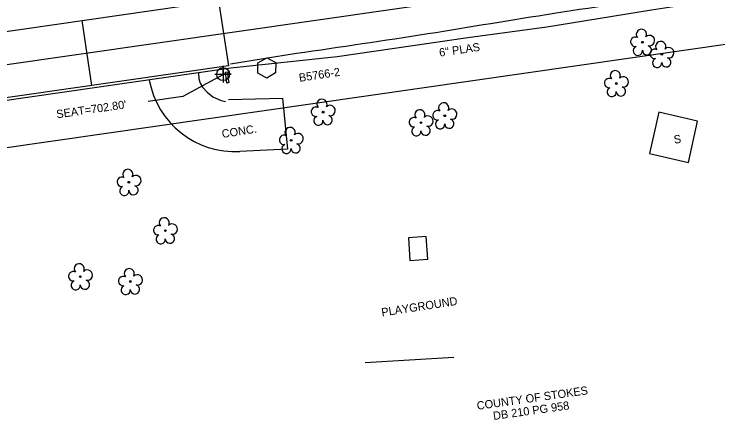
# Model space of a CAD drawing. Extents: x 1645945 to 2447332, y 713118 to 970361.
# Drawn here: x 1646888.7 to 1647146.3, y 969388.4 to 969536.8 of the extents above; entities that cross this region are included whole.
import ezdxf

# ---------------------------------------------------------------- set-up
doc = ezdxf.new("R2010")
doc.units = 0
for name, color, linetype in [('CTL Primary Horizontal and Vertical CELL', 7, 'Continuous'), ('CTL Primary Horizontal and Vertical Text', 7, 'Continuous'), ('Exist Building', 7, 'Continuous'), ('Exist Horizontal Alignment', 7, 'Continuous'), ('Exist Other Culture Area Outline', 7, 'Continuous'), ('Exist Other Culture Area Outline Text', 7, 'Continuous'), ('Exist Property Deed Book Text', 7, 'Continuous'), ('Exist Property Owner Text', 7, 'Continuous'), ('Exist Right of Way Line', 7, 'Continuous'), ('Exist Roads EOP', 7, 'Continuous'), ('Exist Structure Major Bridge Seam', 7, 'Continuous'), ('Exist Structure Major Bridge Seat Cogo Point CELL', 7, 'Continuous'), ('Exist Structure Major Bridge Seat Leader', 7, 'Continuous'), ('Exist Structure Major Bridge Seat Top Elevation', 7, 'Continuous'), ('Exist Structure Major Bridge WW', 7, 'Continuous'), ('Exist Structure Major Deck Tunnel Box Culvert', 7, 'Continuous'), ('Exist Utilities Sanitary Sewer Forced Main SUE LOS B', 7, 'Continuous'), ('Exist Utilities Sanitary Sewer Forced Main SUE LOS B Text', 7, 'Continuous'), ('Exist Utilities Sanitary Sewer Forced Main SUE LOS C', 7, 'Continuous'), ('Exist Vegetation Tree CELL', 7, 'Continuous')]:
    doc.layers.add(name, color=color, linetype=linetype)

msp = doc.modelspace()

# ---------------------------------------------------------------- linework, layer by layer
at = {"layer": 'CTL Primary Horizontal and Vertical CELL'}
msp.add_line((1646981.23, 969517.14), (1646981.23, 969517.14), dxfattribs=at)
msp.add_lwpolyline([(1646978, 969519.01), (1646981.25, 969520.82), (1646984.5, 969519.03), (1646984.45, 969515.31), (1646981.2, 969513.42), (1646978, 969515.23)], close=True, dxfattribs=at)
at = {"layer": 'Exist Building'}
msp.add_lwpolyline([(1647124.68, 969500.9), (1647121.22, 969485.85), (1647135.61, 969482.53), (1647138.83, 969497.65)], close=True, dxfattribs=at)
at = {"layer": 'Exist Horizontal Alignment'}
msp.add_line((1646298.92, 969433.93), (1647141.43, 969555.05), dxfattribs=at)
at = {"layer": 'Exist Other Culture Area Outline'}
msp.add_line((1647017.24, 969409.4), (1647049.61, 969411.4), dxfattribs=at)
for points in [[(1646956.19, 969515.23), (1646956.39, 969513.13), (1646956.89, 969511.58), (1646957.71, 969510.07), (1646959.36, 969508.27), (1646961.44, 969506.6), (1646964.56, 969505.2), (1646966.05, 969504.79)], [(1646967.24, 969505.55), (1646986.92, 969506.01), (1646988.76, 969487.37), (1646971.39, 969486.58)]]:
    msp.add_lwpolyline(points, dxfattribs=at)
msp.add_lwpolyline([(1647033.62, 969446.69), (1647040.13, 969447.17), (1647039.54, 969455.54), (1647033.02, 969455.06)], close=True, dxfattribs=at)
msp.add_arc((1646969.57, 969518.46), 31.93, 190.4277, 273.2578, dxfattribs=at)
at = {"layer": 'Exist Right of Way Line'}
msp.add_line((1646441.61, 969424.14), (1647154.4, 969526.61), dxfattribs=at)
at = {"layer": 'Exist Roads EOP'}
msp.add_line((1646992.05, 969522.32), (1646967.96, 969518.43), dxfattribs=at)
msp.add_spline([(1647731.3, 969935.45), (1647707.71, 969895.07), (1647684.27, 969857.13), (1647654.38, 969814.5), (1647624.46, 969779.25), (1647589.97, 969744.66), (1647553.5, 969714.01), (1647512.43, 969684.95), (1647469.3, 969658.19), (1647421.26, 969632.07), (1647375.68, 969609.9), (1647329.15, 969590.49), (1647286.02, 969576.26), (1647230.19, 969561.18), (1647183.04, 969552.75), (1647135.89, 969544.58), (1647086.4, 969536.99), (1647040.14, 969529.53), (1646992.05, 969522.32)], degree=3, dxfattribs=at)
at = {"layer": 'Exist Structure Major Bridge Seam'}
msp.add_line((1646913.54, 969534.4), (1646917.09, 969510.7), dxfattribs=at)
at = {"layer": 'Exist Structure Major Bridge Seat Cogo Point CELL'}
msp.add_lwpolyline([(1646962.24, 969514.82), (1646968.24, 969514.82), (1646965.24, 969514.82), (1646965.24, 969517.82), (1646965.24, 969511.82)], dxfattribs=at)
msp.add_circle((1646965.24, 969514.82), 2.34, dxfattribs=at)
at = {"layer": 'Exist Structure Major Bridge Seat Leader'}
msp.add_lwpolyline([(1646965.12, 969514.64), (1646950.54, 969506.66), (1646937.85, 969504.84)], dxfattribs=at)
at = {"layer": 'Exist Structure Major Bridge WW'}
msp.add_lwpolyline([(1646966.11, 969515.53), (1646966.98, 969515.63), (1646967.01, 969513.65), (1646967.38, 969511.73), (1646966.56, 969511.58), (1646966.32, 969513.6), (1646966.11, 969515.53)], dxfattribs=at)
at = {"layer": 'Exist Structure Major Deck Tunnel Box Culvert'}
msp.add_lwpolyline([(1646967.24, 969517.89), (1646619.97, 969468.05), (1646615.96, 969491.55), (1646963.57, 969541.6), (1646967.24, 969517.89)], dxfattribs=at)
at = {"layer": 'Exist Utilities Sanitary Sewer Forced Main SUE LOS B'}
msp.add_lwpolyline([(1646968.01, 969517.18), (1647007.02, 969521.34), (1647054.78, 969528.26), (1647083.72, 969532.15), (1647121.99, 969538.31), (1647141.01, 969541.29), (1647166.59, 969544.9), (1647192.95, 969550.61), (1647220.41, 969556.52), (1647247.21, 969563.1), (1647258.95, 969564.71), (1647268.16, 969566.61), (1647282, 969570.9)], dxfattribs=at)
at = {"layer": 'Exist Utilities Sanitary Sewer Forced Main SUE LOS C'}
msp.add_line((1646620.32, 969466.68), (1646968.01, 969517.18), dxfattribs=at)
at = {"layer": 'Exist Vegetation Tree CELL'}
for p, q in [((1647118.7, 969526.49), (1647118.7, 969526.49)), ((1647125.78, 969522.07), (1647125.78, 969522.07)), ((1647109.13, 969511.42), (1647109.13, 969511.42)), ((1647001.81, 969500.95), (1647001.81, 969500.95)), ((1647046.35, 969499.63), (1647046.35, 969499.63)), ((1647037.66, 969497.1), (1647037.66, 969497.1)), ((1646990.13, 969490.65), (1646990.13, 969490.65)), ((1646930.77, 969475.31), (1646930.77, 969475.31)), ((1646944.09, 969457.62), (1646944.09, 969457.62)), ((1646912.99, 969440.8), (1646912.99, 969440.8)), ((1646931.28, 969439.04), (1646931.28, 969439.04))]:
    msp.add_line(p, q, dxfattribs=at)
for centre in [(1647118.7, 969526.49), (1647125.78, 969522.07), (1647109.13, 969511.42), (1647001.81, 969500.95), (1647046.35, 969499.63), (1647037.66, 969497.1), (1646990.13, 969490.65), (1646930.77, 969475.31), (1646944.09, 969457.62), (1646912.99, 969440.8), (1646931.28, 969439.04)]:
    msp.add_circle(centre, 0.326, dxfattribs=at)
for centre, radius, start, end in [((1647118.31, 969529.37), 1.86, 330.1651, 219.7134), ((1647116.09, 969526.65), 1.73, 62.6636, 279.3457), ((1647121.25, 969527.08), 1.9, 257.1011, 134.1999), ((1647125.39, 969524.94), 1.86, 330.1651, 219.7134), ((1647117, 969523.37), 1.69, 111.5671, 6.231), ((1647120.37, 969523.59), 1.7, 181.2822, 74.56), ((1647123.17, 969522.22), 1.73, 62.6636, 279.3457), ((1647128.33, 969522.66), 1.9, 257.1011, 134.1999), ((1647127.45, 969519.17), 1.7, 181.2822, 74.56), ((1647124.08, 969518.95), 1.69, 111.5671, 6.231), ((1647108.75, 969514.29), 1.86, 330.1651, 219.7134), ((1647106.53, 969511.57), 1.73, 62.6636, 279.3457), ((1647111.68, 969512), 1.9, 257.1011, 134.1999), ((1647107.43, 969508.3), 1.69, 111.5671, 6.231), ((1647110.81, 969508.52), 1.7, 181.2822, 74.56), ((1647001.42, 969503.83), 1.86, 330.1651, 219.7134), ((1646999.2, 969501.11), 1.73, 62.6636, 279.3457), ((1647004.36, 969501.54), 1.9, 257.1011, 134.1999), ((1647045.96, 969502.5), 1.86, 330.1651, 219.7134), ((1647037.27, 969499.97), 1.86, 330.1651, 219.7134), ((1647043.74, 969499.78), 1.73, 62.6636, 279.3457), ((1647048.9, 969500.22), 1.9, 257.1011, 134.1999), ((1647000.1, 969497.83), 1.69, 111.5671, 6.231), ((1647003.48, 969498.05), 1.7, 181.2822, 74.56), ((1647035.05, 969497.25), 1.73, 62.6636, 279.3457), ((1647040.21, 969497.69), 1.9, 257.1011, 134.1999), ((1647044.65, 969496.51), 1.69, 111.5671, 6.231), ((1647048.02, 969496.73), 1.7, 181.2822, 74.56), ((1646989.74, 969493.52), 1.86, 330.1651, 219.7134), ((1647035.95, 969493.98), 1.69, 111.5671, 6.231), ((1647039.33, 969494.2), 1.7, 181.2822, 74.56), ((1646987.52, 969490.8), 1.73, 62.6636, 279.3457), ((1646992.68, 969491.24), 1.9, 257.1011, 134.1999), ((1646988.42, 969487.53), 1.69, 111.5671, 6.231), ((1646991.8, 969487.75), 1.7, 181.2822, 74.56), ((1646930.38, 969478.19), 1.86, 330.1651, 219.7134), ((1646928.16, 969475.47), 1.73, 62.6636, 279.3457), ((1646933.32, 969475.9), 1.9, 257.1011, 134.1999), ((1646929.07, 969472.19), 1.69, 111.5671, 6.231), ((1646932.44, 969472.41), 1.7, 181.2822, 74.56), ((1646943.71, 969460.49), 1.86, 330.1651, 219.7134), ((1646941.49, 969457.77), 1.73, 62.6636, 279.3457), ((1646946.64, 969458.21), 1.9, 257.1011, 134.1999), ((1646945.76, 969454.72), 1.7, 181.2822, 74.56), ((1646942.39, 969454.5), 1.69, 111.5671, 6.231), ((1646912.6, 969443.67), 1.86, 330.1651, 219.7134), ((1646930.89, 969441.91), 1.86, 330.1651, 219.7134), ((1646910.38, 969440.95), 1.73, 62.6636, 279.3457), ((1646915.54, 969441.39), 1.9, 257.1011, 134.1999), ((1646928.67, 969439.19), 1.73, 62.6636, 279.3457), ((1646933.82, 969439.62), 1.9, 257.1011, 134.1999), ((1646911.29, 969437.68), 1.69, 111.5671, 6.231), ((1646914.66, 969437.9), 1.7, 181.2822, 74.56), ((1646929.57, 969435.92), 1.69, 111.5671, 6.231), ((1646932.95, 969436.14), 1.7, 181.2822, 74.56)]:
    msp.add_arc(centre, radius, start, end, dxfattribs=at)

# ---------------------------------------------------------------- texts
at = {"layer": 'CTL Primary Horizontal and Vertical Text'}
msp.add_text('B5766-2', height=3, rotation=8.5829, dxfattribs=at).set_placement((1646993.2, 969512.01))
at = {"layer": 'Exist Other Culture Area Outline Text'}
for s, p in [('CONC.', (1646964.98, 969491.49)), ('S', (1647130.4, 969489.39)), ('PLAYGROUND', (1647023.4, 969426.24))]:
    msp.add_text(s, height=3, rotation=8.7749, dxfattribs=at).set_placement(p)
at = {"layer": 'Exist Property Deed Book Text'}
msp.add_text('DB 210 PG 958', height=3, rotation=8.0451, dxfattribs=at).set_placement((1647064.25, 969388.4))
at = {"layer": 'Exist Property Owner Text'}
msp.add_text('COUNTY OF STOKES', height=3, rotation=8.0451, dxfattribs=at).set_placement((1647058.29, 969392.1))
at = {"layer": 'Exist Structure Major Bridge Seat Top Elevation'}
msp.add_text("SEAT=702.80'", height=3, rotation=8.1623, dxfattribs=at).set_placement((1646904.4, 969498.67))
at = {"layer": 'Exist Utilities Sanitary Sewer Forced Main SUE LOS B Text'}
msp.add_text('6" PLAS', height=3, rotation=8.2358, dxfattribs=at).set_placement((1647044.52, 969521.21))

doc.saveas('drawing.dxf')
